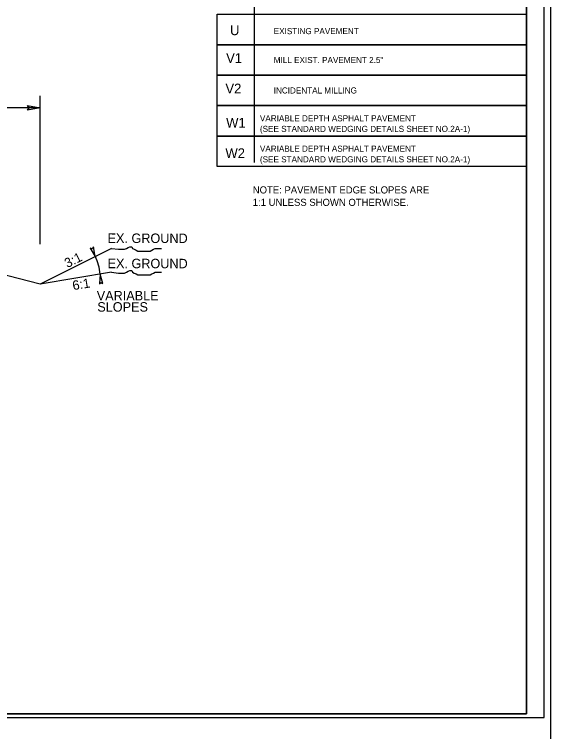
# Model space of a CAD drawing. Extents: x 2320980 to 2456309, y 595047 to 606177.
# Drawn here: x 2455970.1 to 2456045.5, y 596086.6 to 596187.4 of the extents above; entities that cross this region are included whole.
import ezdxf

# ---------------------------------------------------------------- set-up
doc = ezdxf.new("R2010")
doc.units = 0
for name, color, linetype in [('Old_Level_1', 7, 'Continuous'), ('Old_Level_11', 7, 'Continuous'), ('Old_Level_21', 7, 'Continuous'), ('Prop Dimension', 7, 'Continuous'), ('Prop Pavement Schedule Description CELL', 7, 'Continuous'), ('Sheet Plan CELL', 7, 'Continuous'), ('Sheet Plot Border Inside CELL', 7, 'Continuous'), ('Sheet Plot Border Outside CELL', 7, 'Continuous'), ('Typical Hinge Slope Arterial CELL', 7, 'Continuous'), ('Typical Terminator CELL', 7, 'Continuous')]:
    doc.layers.add(name, color=color, linetype=linetype)

msp = doc.modelspace()

# ---------------------------------------------------------------- linework, layer by layer
at = {"layer": 'Old_Level_11'}
msp.add_lwpolyline([(2455971.97, 596174.58), (2455973.77, 596174.27), (2455971.96, 596173.95), (2455972.19, 596174.27)], close=True, dxfattribs=at)
at = {"layer": 'Old_Level_21'}
msp.add_line((2455973.77, 596155.08), (2455973.77, 596175.96), dxfattribs=at)
at = {"layer": 'Prop Dimension'}
for p, q in [((2456003.83, 596260.09), (2456003.83, 596166.59)), ((2455973.77, 596174.27), (2455961.77, 596174.27))]:
    msp.add_line(p, q, dxfattribs=at)
for points in [[(2455998.64, 596187.4), (2456042.11, 596187.4), (2456042.11, 596183.12), (2455998.64, 596183.12)], [(2455998.64, 596183.12), (2456042.11, 596183.12), (2456042.11, 596178.84), (2455998.64, 596178.84)], [(2455998.64, 596178.84), (2456042.11, 596178.84), (2456042.11, 596174.57), (2455998.64, 596174.57)], [(2455998.64, 596174.57), (2456042.11, 596174.57), (2456042.11, 596170.29), (2455998.64, 596170.29)], [(2455998.64, 596170.29), (2456042.11, 596170.29), (2456042.11, 596166.01), (2455998.64, 596166.01)]]:
    msp.add_lwpolyline(points, close=True, dxfattribs=at)
at = {"layer": 'Prop Pavement Schedule Description CELL'}
msp.add_line((2455998.64, 596166.01), (2455998.64, 596166.01), dxfattribs=at)
at = {"layer": 'Sheet Plan CELL'}
for points in [[(2456042.11, 596299.08), (2455742.1, 596299.08), (2455742.1, 596089.08), (2456042.11, 596089.08)], [(2455742.1, 596089.08), (2455742.1, 596299.07), (2456002.1, 596299.08), (2456002.1, 596269.07), (2456042.11, 596269.06), (2456042.11, 596089.08)]]:
    msp.add_lwpolyline(points, close=True, dxfattribs=at)
at = {"layer": 'Sheet Plot Border Inside CELL'}
msp.add_lwpolyline([(2455711.41, 596088.57), (2456044.6, 596088.58), (2456044.61, 596299.57), (2455711.41, 596299.57)], close=True, dxfattribs=at)
at = {"layer": 'Sheet Plot Border Outside CELL'}
msp.add_lwpolyline([(2455708.81, 596084.57), (2456045.51, 596084.57), (2456045.51, 596303.57), (2455708.81, 596303.57)], close=True, dxfattribs=at)
at = {"layer": 'Typical Hinge Slope Arterial CELL'}
for p, q in [((2455983.77, 596154.49), (2455973.77, 596149.49)), ((2455973.77, 596149.49), (2455961.92, 596152.45)), ((2455983.77, 596151.16), (2455973.77, 596149.49))]:
    msp.add_line(p, q, dxfattribs=at)
for points in [[(2455983.77, 596154.49), (2455984.76, 596154.37), (2455985, 596154.37), (2455985.37, 596154.37), (2455985.62, 596154.37), (2455985.87, 596154.49), (2455986.11, 596154.61), (2455986.36, 596154.74), (2455986.61, 596154.74), (2455986.73, 596154.49), (2455986.98, 596154.37), (2455987.22, 596154.24), (2455987.47, 596154.12), (2455987.71, 596154.12), (2455987.96, 596154.12), (2455988.21, 596154.12), (2455988.45, 596154.12), (2455988.7, 596154.12), (2455988.95, 596154.12), (2455989.19, 596154.12), (2455989.44, 596154.24), (2455989.69, 596154.37), (2455989.93, 596154.49), (2455990.3, 596154.49), (2455990.55, 596154.49), (2455990.79, 596154.49)], [(2455983.77, 596151.16), (2455984.76, 596151.03), (2455985, 596151.03), (2455985.37, 596151.03), (2455985.62, 596151.03), (2455985.87, 596151.16), (2455986.11, 596151.28), (2455986.36, 596151.4), (2455986.61, 596151.4), (2455986.73, 596151.16), (2455986.98, 596151.03), (2455987.22, 596150.91), (2455987.47, 596150.79), (2455987.71, 596150.79), (2455987.96, 596150.79), (2455988.21, 596150.79), (2455988.45, 596150.79), (2455988.7, 596150.79), (2455988.95, 596150.79), (2455989.19, 596150.79), (2455989.44, 596150.91), (2455989.69, 596151.03), (2455989.93, 596151.16), (2455990.3, 596151.16), (2455990.55, 596151.16), (2455990.79, 596151.16)]]:
    msp.add_lwpolyline(points, dxfattribs=at)
msp.add_arc((2455974.48, 596150.11), 7.74, 5.8103, 24.8127, dxfattribs=at)
at = {"layer": 'Typical Terminator CELL'}
for points in [[(2455980.79, 596154.53), (2455981.5, 596153.35), (2455981.23, 596154.71), (2455981.07, 596154.46)], [(2455982.57, 596149.58), (2455982.17, 596150.89), (2455982.1, 596149.51), (2455982.32, 596149.71)]]:
    msp.add_lwpolyline(points, close=True, dxfattribs=at)

# ---------------------------------------------------------------- texts
at = {"layer": 'Old_Level_1'}
for p in [(2455983.22, 596155.27), (2455983.22, 596151.72)]:
    msp.add_text('EX. GROUND', height=1.33, rotation=359.9103, dxfattribs=at).set_placement(p)
at = {"layer": 'Prop Pavement Schedule Description CELL'}
for s, height, p in [('U', 1.37, (2456000.44, 596184.47)), ('EXISTING PAVEMENT', 0.8552, (2456006.58, 596184.61)), ('V1', 1.368, (2455999.89, 596180.57)), ('MILL EXIST. PAVEMENT 2.5"', 0.8552, (2456006.58, 596180.55)), ('V2', 1.368, (2455999.79, 596176.29)), ('INCIDENTAL MILLING', 0.8552, (2456006.58, 596176.27)), ('W1', 1.368, (2455999.89, 596171.48)), ('VARIABLE DEPTH ASPHALT PAVEMENT', 0.8552, (2456004.64, 596172.36)), ('(SEE STANDARD WEDGING DETAILS SHEET NO.2A-1)', 0.8552, (2456004.64, 596170.87)), ('W2', 1.368, (2455999.79, 596167.2)), ('VARIABLE DEPTH ASPHALT PAVEMENT', 0.8552, (2456004.64, 596168.09)), ('(SEE STANDARD WEDGING DETAILS SHEET NO.2A-1)', 0.8552, (2456004.64, 596166.59)), ('NOTE: PAVEMENT EDGE SLOPES ARE', 0.9998, (2456003.63, 596162.22)), ('1:1 UNLESS SHOWN OTHERWISE.', 0.9998, (2456003.63, 596160.47))]:
    msp.add_text(s, height=height, dxfattribs=at).set_placement(p)
at = {"layer": 'Typical Hinge Slope Arterial CELL'}
for s, rotation, p in [('3:1', 26.565, (2455977.57, 596151.72)), ('6:1', 9.4635, (2455978.4, 596148.61))]:
    msp.add_text(s, height=1.33, rotation=rotation, dxfattribs=at).set_placement(p)
for s, p in [('VARIABLE ', (2455981.7, 596147.19)), ('SLOPES', (2455981.78, 596145.61))]:
    msp.add_text(s, height=1.33, dxfattribs=at).set_placement(p)

doc.saveas('drawing.dxf')
